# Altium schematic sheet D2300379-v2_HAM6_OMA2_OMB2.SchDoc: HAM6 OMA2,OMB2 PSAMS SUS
size C; Engineer: L. Sanchez; Organization: LIGO Laboratory; Address1: California Institute of Technology; Address2: Massachusetts Institute of Technology; DocumentNumber: D2300379; Revision: v1; SheetNumber: 3; SheetTotal: 9
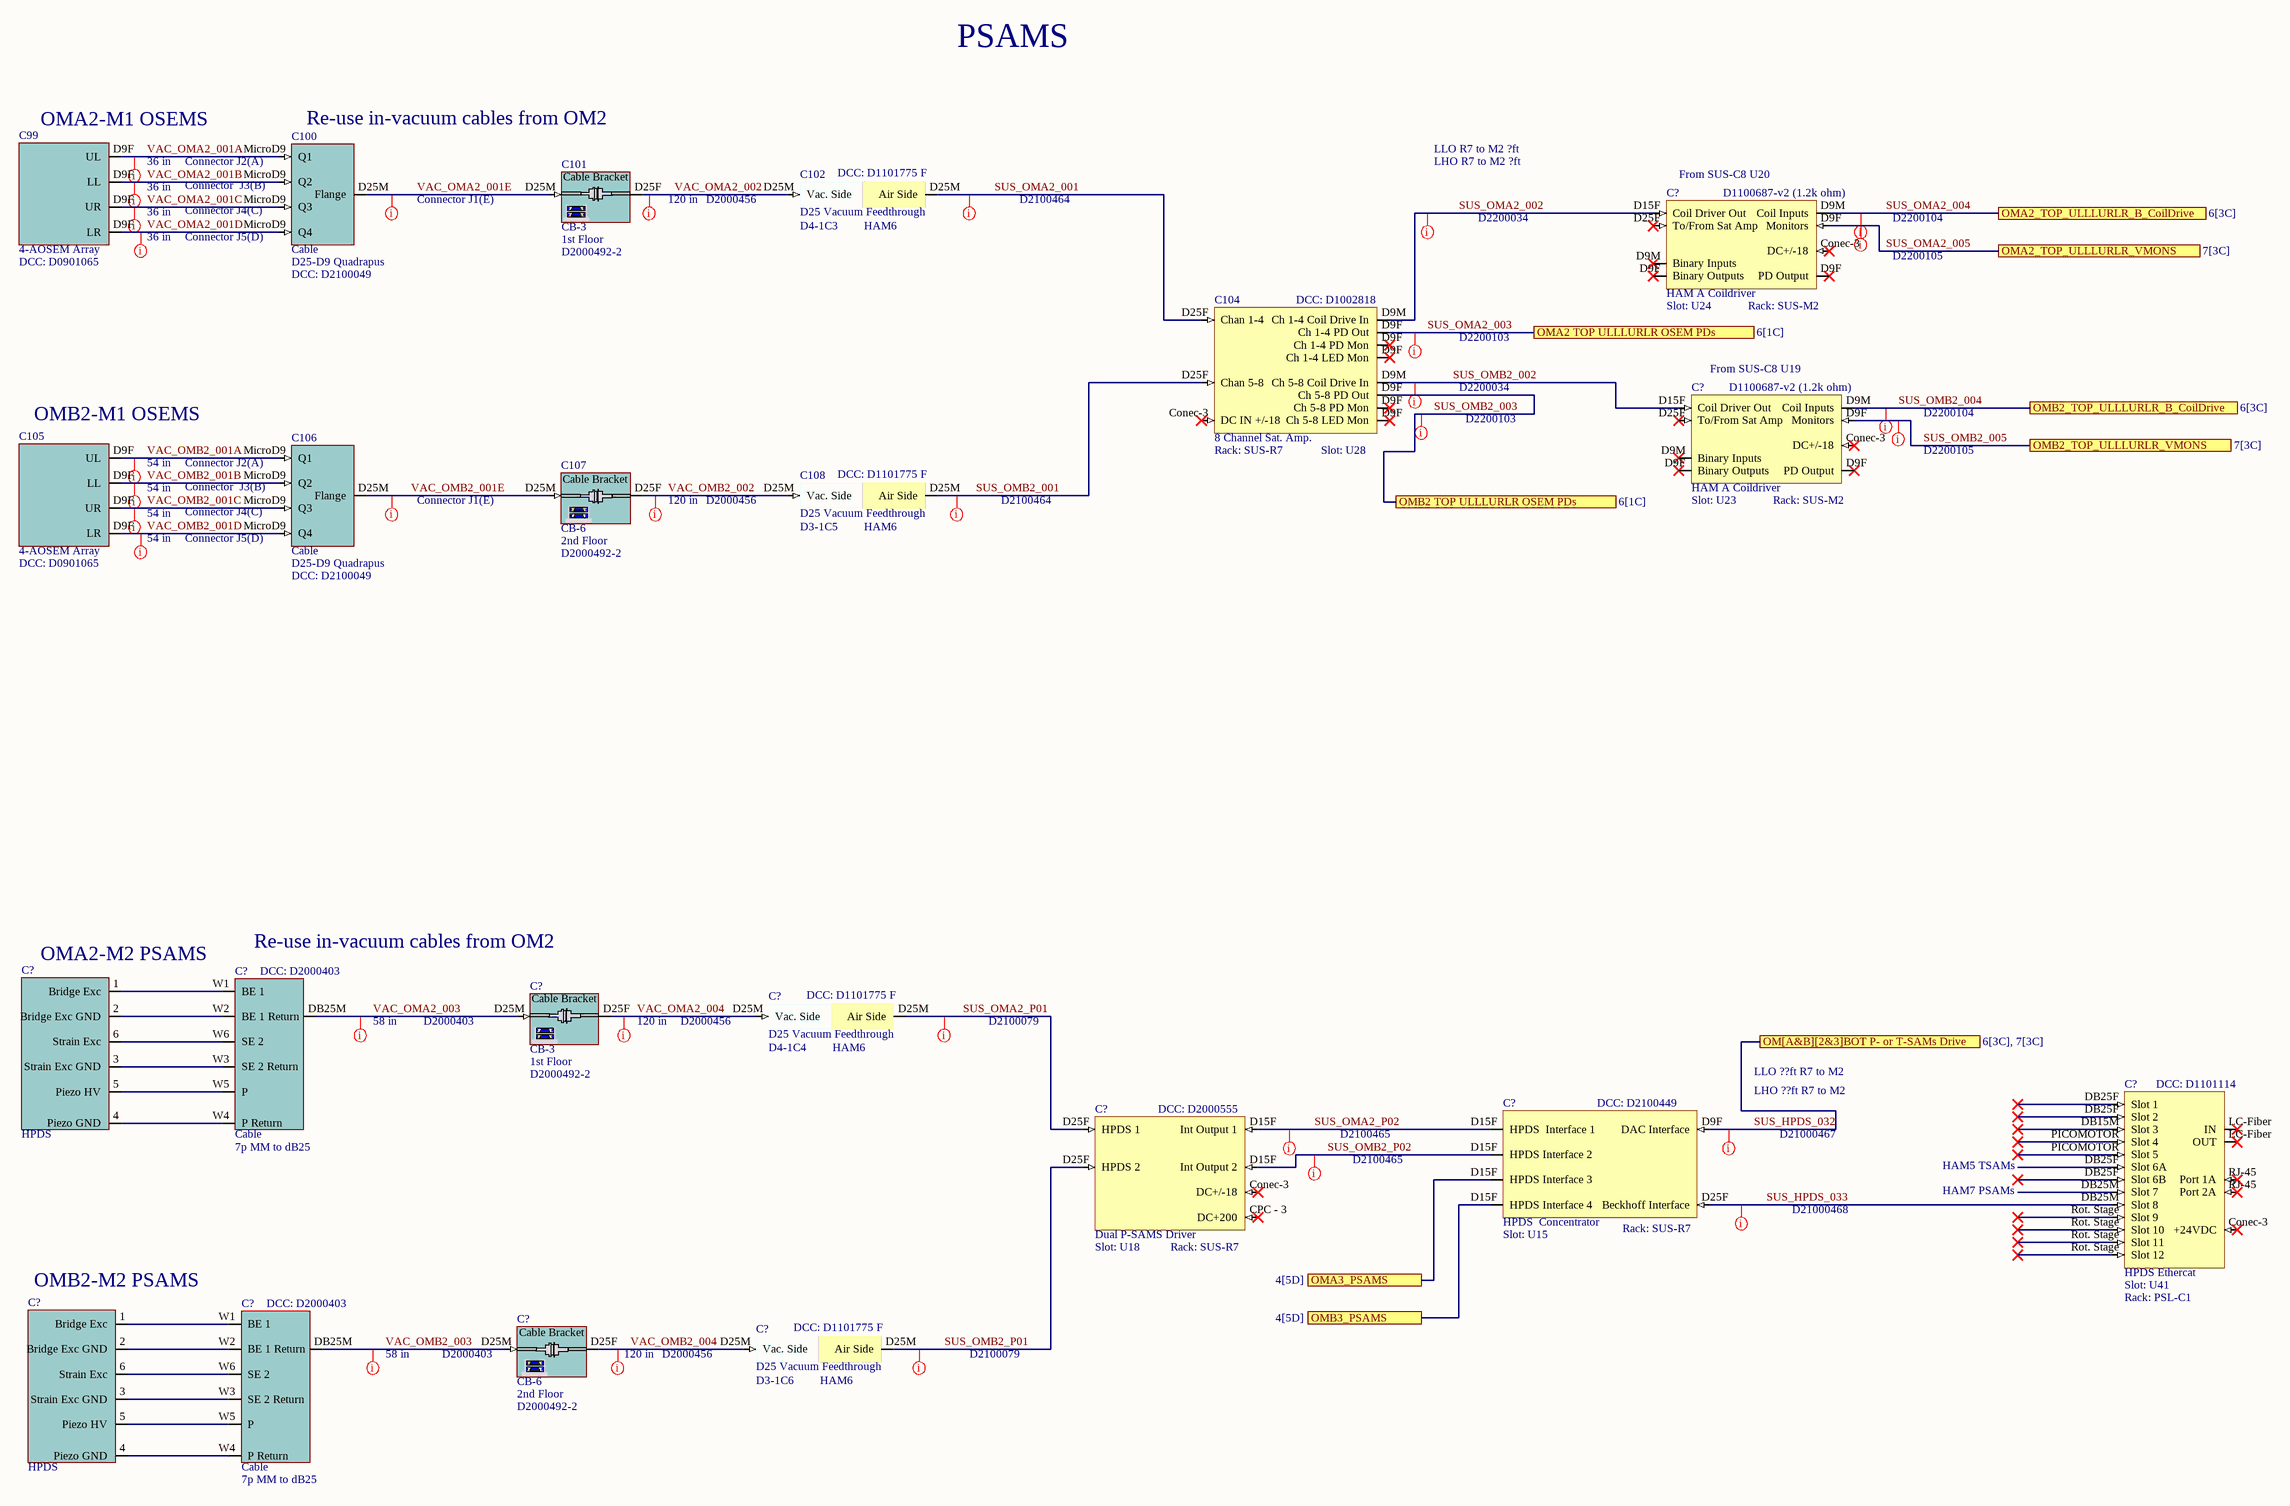
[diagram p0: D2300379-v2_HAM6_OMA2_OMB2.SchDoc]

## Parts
(Parts that share a designator on the sheet are numbered #1, #2 ... from top to bottom, then left to right.)
C99  4-AOSEM Array  DCC: D0901065
C100  Cable  value D25-D9 Quadrapus  DCC: D2100049
C101  Rack: CB-3  Slot: 1st Floor  DCC: D2000492-2  (hidden comment: Cable Bracket)
C102  D25 Vacuum Feedthrough  DCC: D1101775 F  Feedthrough: D4-1C3  Chamber: HAM6
C104  8 Channel Sat. Amp.  DCC: D1002818  Rack: SUS-R7  Slot: U28
C105  4-AOSEM Array  DCC: D0901065
C106  Cable  value D25-D9 Quadrapus  DCC: D2100049
C107  Rack: CB-6  Slot: 2nd Floor  DCC: D2000492-2  (hidden comment: Cable Bracket)
C108  D25 Vacuum Feedthrough  DCC: D1101775 F  Feedthrough: D3-1C5  Chamber: HAM6
C?#1  HAM A Coildriver  Rack: SUS-M2  Slot: U24
C?#2  HAM A Coildriver  Rack: SUS-M2  Slot: U23
C?#3  Rack: CB-3  Slot: 1st Floor  DCC: D2000492-2  (hidden comment: Cable Bracket)
C?#4  D25 Vacuum Feedthrough  DCC: D1101775 F  Feedthrough: D4-1C4  Chamber: HAM6
C?#5  Cable  value 7p MM to dB25  DCC: D2000403
C?#6  HPDS
C?#7  HPDS  Concentrator  Slot: U15  Rack: SUS-R7  DCC: D2100449
C?#8  Dual P-SAMS Driver  Slot: U18  Rack: SUS-R7  DCC: D2000555
C?#9  HPDS Ethercat  Slot: U41  Rack: PSL-C1  DCC: D1101114
C?#10  Rack: CB-6  Slot: 2nd Floor  DCC: D2000492-2  (hidden comment: Cable Bracket)
C?#11  D25 Vacuum Feedthrough  DCC: D1101775 F  Feedthrough: D3-1C6  Chamber: HAM6
C?#12  Cable  value 7p MM to dB25  DCC: D2000403
C?#13  HPDS

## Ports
OM[A&B][2&3]BOT P- or T-SAMs Drive (see 6[3C], 7[3C]), OMA2 TOP ULLLURLR OSEM PDs (see 6[1C]), OMA2_TOP_ULLLURLR_B_CoilDrive (see 6[3C]), OMA2_TOP_ULLLURLR_VMONS (see 7[3C]), OMA3_PSAMS (see 4[5D]), OMB2 TOP ULLLURLR OSEM PDs (see 6[1C]), OMB2_TOP_ULLLURLR_B_CoilDrive (see 6[3C]), OMB2_TOP_ULLLURLR_VMONS (see 7[3C]), OMB3_PSAMS (see 4[5D])

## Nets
OMA3_PSAMS: C?#7.D15F(HPDS_Interface_3) ; port OMA3_PSAMS
OMB3_PSAMS: C?#7.D15F(HPDS_Interface_4) ; port OMB3_PSAMS
SUS_HPDS_032: C?#7.D9F(DAC_Interface) ; port OM[A&B][2&3]BOT P- or T-SAMs Drive
SUS_HPDS_033: C?#7.D25F(Beckhoff_Interface) C?#9.DB25M(Slot_8)
SUS_OMA2_001: C102.D25M(Air_Side) C104.D25F(Chan_1-4)
SUS_OMA2_002: C104.D9M(Ch_1-4_Coil_Drive_In) C?#1.D15F(Coil_Driver_Out)
SUS_OMA2_003: C104.D9F(Ch_1-4_PD_Out) ; port OMA2 TOP ULLLURLR OSEM PDs
SUS_OMA2_004: C?#1.D9M(Coil_Inputs) ; port OMA2_TOP_ULLLURLR_B_CoilDrive
SUS_OMA2_005: C?#1.D9F(PD_Output) ; port OMA2_TOP_ULLLURLR_VMONS
SUS_OMA2_P01: C?#4.D25M(Air_Side) C?#8.D25F(HPDS_1)
SUS_OMA2_P02: C?#7.D15F(HPDS__Interface_1) C?#8.D15F(Int_Output_1)
SUS_OMB2_001: C104.D25F(Chan_5-8) C108.D25M(Air_Side)
SUS_OMB2_002: C104.D9M(Ch_5-8_Coil_Drive_In) C?#2.D15F(Coil_Driver_Out)
SUS_OMB2_003: C104.D9F(Ch_5-8_PD_Out) ; port OMB2 TOP ULLLURLR OSEM PDs
SUS_OMB2_004: C?#2.D9M(Coil_Inputs) ; port OMB2_TOP_ULLLURLR_B_CoilDrive
SUS_OMB2_005: C?#2.D9F(PD_Output) ; port OMB2_TOP_ULLLURLR_VMONS
SUS_OMB2_P01: C?#8.D25F(HPDS_2) C?#11.D25M(Air_Side)
SUS_OMB2_P02: C?#7.D15F(HPDS_Interface_2) C?#8.D15F(Int_Output_2)
VAC_OMA2_001A: C99.D9F(UL) C100.MicroD9(Q1)
VAC_OMA2_001B: C99.D9F(LL) C100.MicroD9(Q2)
VAC_OMA2_001C: C99.D9F(UR) C100.MicroD9(Q3)
VAC_OMA2_001D: C99.D9F(LR) C100.MicroD9(Q4)
VAC_OMA2_001E: C100.D25M(Flange) C101.D25M
VAC_OMA2_002: C101.D25F C102.D25M(Vac._Side)
VAC_OMA2_003: C?#3.D25M C?#5.DB25M
VAC_OMA2_004: C?#3.D25F C?#4.D25M(Vac._Side)
VAC_OMB2_001A: C105.D9F(UL) C106.MicroD9(Q1)
VAC_OMB2_001B: C105.D9F(LL) C106.MicroD9(Q2)
VAC_OMB2_001C: C105.D9F(UR) C106.MicroD9(Q3)
VAC_OMB2_001D: C105.D9F(LR) C106.MicroD9(Q4)
VAC_OMB2_001E: C106.D25M(Flange) C107.D25M
VAC_OMB2_002: C107.D25F C108.D25M(Vac._Side)
VAC_OMB2_003: C?#10.D25M C?#12.DB25M
VAC_OMB2_004: C?#10.D25F C?#11.D25M(Vac._Side)
NetC?#5_W1: C?#5.W1(BE_1) C?#6.1(Bridge_Exc)
NetC?#5_W2: C?#5.W2(BE_1_Return) C?#6.2(Bridge_Exc_GND)
NetC?#5_W3: C?#5.W3(SE_2_Return) C?#6.3(Strain_Exc_GND)
NetC?#5_W4: C?#5.W4(P_Return) C?#6.4(Piezo_GND)
NetC?#5_W5: C?#5.W5(P) C?#6.5(Piezo_HV)
NetC?#5_W6: C?#5.W6(SE_2) C?#6.6(Strain_Exc)
NetC?#12_W1: C?#12.W1(BE_1) C?#13.1(Bridge_Exc)
NetC?#12_W2: C?#12.W2(BE_1_Return) C?#13.2(Bridge_Exc_GND)
NetC?#12_W3: C?#12.W3(SE_2_Return) C?#13.3(Strain_Exc_GND)
NetC?#12_W4: C?#12.W4(P_Return) C?#13.4(Piezo_GND)
NetC?#12_W5: C?#12.W5(P) C?#13.5(Piezo_HV)
NetC?#12_W6: C?#12.W6(SE_2) C?#13.6(Strain_Exc)

Not connected (* = marked no-connect by the designer): C104 Conec-3(DC_IN_+/-18)*; C?#1 Conec-3(DC+/-18)* D25F(To/From_Sat_Amp)*; C?#2 Conec-3(DC+/-18)* D25F(To/From_Sat_Amp)*; C?#8 Conec-3(DC+/-18)* CPC - 3(DC+200)*; C?#9 Conec-3(+24VDC)* DB15M(Slot_3)* DB25F(Slot_1)* LC-Fiber(IN)* PICOMOTOR(Slot_4)* RJ-45(Port_1A)* Rot. Stage(Slot_9)*

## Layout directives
DCC: Connector J5(D): VAC_OMA2_001D, VAC_OMB2_001D
DCC: Connector J2(A): VAC_OMA2_001A, VAC_OMB2_001A
DCC: Connector  J3(B): VAC_OMA2_001B, VAC_OMB2_001B
DCC: Connector J4(C): VAC_OMA2_001C, VAC_OMB2_001C
DCC: D2000456: VAC_OMA2_002, VAC_OMA2_004, VAC_OMB2_002, VAC_OMB2_004
Length: 5; DCC: Connector J1(E): VAC_OMA2_001E, VAC_OMB2_001E
DCC: D2200103: SUS_OMA2_003, SUS_OMB2_003
DCC: D2200034: SUS_OMA2_002, SUS_OMB2_002
DCC: D2200104: SUS_OMA2_004, SUS_OMB2_004
DCC: D2200105: SUS_OMA2_005, SUS_OMB2_005
DCC: D2100464: SUS_OMA2_001, SUS_OMB2_001
DCC: D2100079: SUS_OMA2_P01, SUS_OMB2_P01
DCC: D2000403: VAC_OMA2_003, VAC_OMB2_003
DCC: D21000468: SUS_HPDS_033
DCC: D21000467: SUS_HPDS_032
DCC: D2100465: SUS_OMA2_P02, SUS_OMB2_P02

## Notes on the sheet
- PSAMS
- (near C99) OMA2-M1 OSEMS
- (near C100) Re-use in-vacuum cables from OM2
- (near C99) 36 in
- LLO R7 to M2 ?ft
- LHO R7 to M2 ?ft
- (near C?#1) From SUS-C8 U20
- (near C?#1) D1100687-v2 (1.2k ohm)
- (near C101) 120 in
- (near C?#2) From SUS-C8 U19
- (near C?#2) D1100687-v2 (1.2k ohm)
- (near C105) OMB2-M1 OSEMS
- (near C105) 54 in
- (near C107) 120 in
- (near C?#5) Re-use in-vacuum cables from OM2
- (near C?#6) OMA2-M2 PSAMS
- 58 in
- (near C?#3) 120 in
- LLO ??ft R7 to M2
- LHO ??ft R7 to M2
- HAM7 PSAMs
- HAM5 TSAMs
- (near C?#13) OMB2-M2 PSAMS
- (near C?#10) 120 in

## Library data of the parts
C99 = 4-BOSEM Array: Rack: SUS-R?; Serial: Sxxxxxxx; Slot: U?; System: SUS; Parameter: OMA1 HAM6 M1
C100 C106 = Flange: Rack: SUS-R?; Serial: Sxxxxxxx; Slot: U?; System: SUS
C101 C?#3 = D1001347-2 1st Cable Bracket: D1001347-2 1/2 Cable Bracket for BSC Tables; Serial: Sxxxxxxx; System: SUS
C102 C108 C?#4 C?#11 = VacFeedD25: Serial: Sxxxxxxx; System: ISC; Rack: R?; Slot: U?
C104 = 8 Channel Sat. Amp.: Serial: Sxxxxxxx; System: ISC
C105 = 4-BOSEM Array: Rack: SUS-R?; Serial: Sxxxxxxx; Slot: U?; System: SUS; Parameter: OMB1 HAM6 M1
C107 C?#10 = D1001347-2 2nd Cable Bracket: D1001347-2 2/2 Cable Bracket for BSC Tables; Serial: Sxxxxxxx; System: SUS
C?#1 C?#2 = CD HAM-A D1100687: Serial: Sxxxxxxx; System: ISC
C?#5 C?#12 = MM Piezo: Piezo or Thermal; Rack: SUS-R?; Serial: Sxxxxxxx; Slot?: U?; System: SUS
C?#6 C?#13 = HDS+Piezo: HAM Double Suspension with Piezo Driver
C?#7 = HPDS Concentrator: Serial: S?; System: SUS
C?#8 = Dual P-SAMS: Strain Gauge and PZT Driver; Serial: Sxxxxxxx; System: SUS
C?#9 = HPDS Ethercat: PSL - C1; System: MISC; Serial: Sxxxxxxx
